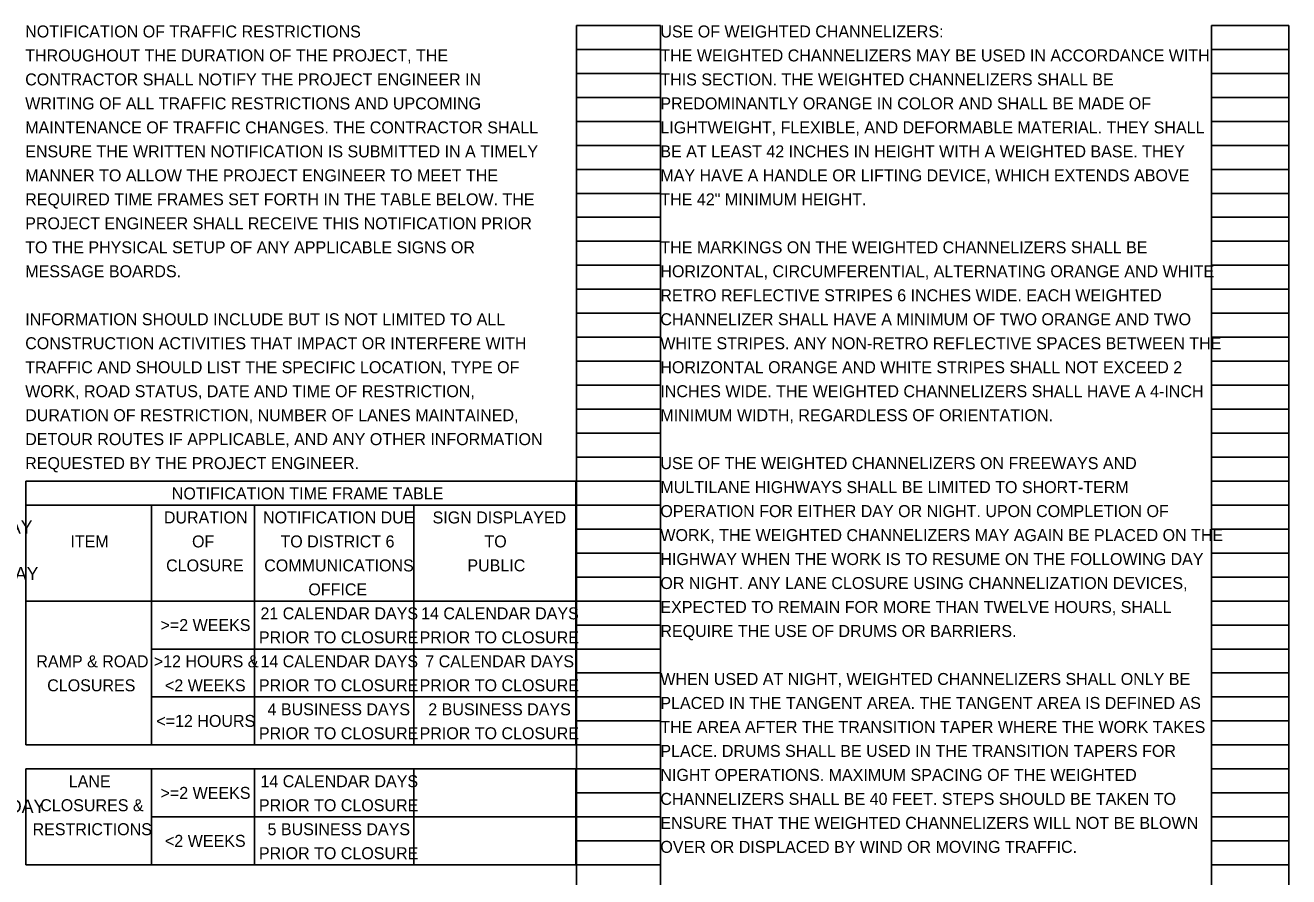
# Model space of a CAD drawing. Extents: x 51924.2 to 51956.2, y 31431.6 to 31530.7.
# Drawn here: x 51941.45 to 51956.21, y 31520.75 to 31530.69 of the extents above; entities that cross this region are included whole.
import ezdxf

# ---------------------------------------------------------------- set-up
doc = ezdxf.new("R2010")
doc.units = 0
doc.layers.add('SH_Data', color=7, linetype='Continuous')
doc.layers.add('SH_Text', color=7, linetype='Continuous')

msp = doc.modelspace()

# ---------------------------------------------------------------- linework, layer by layer
at = {"layer": 'SH_Data'}
for p, q in [((51947.888, 31510.524), (51947.888, 31530.684)), ((51947.888, 31530.684), (51948.868, 31530.684)), ((51948.868, 31510.524), (51948.868, 31530.684)), ((51955.308, 31510.524), (51955.308, 31530.684)), ((51955.308, 31530.684), (51956.208, 31530.684)), ((51956.208, 31510.524), (51956.208, 31530.684)), ((51947.888, 31530.404), (51948.868, 31530.404)), ((51955.308, 31530.404), (51956.208, 31530.404)), ((51947.888, 31530.124), (51948.868, 31530.124)), ((51955.308, 31530.124), (51956.208, 31530.124)), ((51947.888, 31529.844), (51948.868, 31529.844)), ((51955.308, 31529.844), (51956.208, 31529.844)), ((51947.888, 31529.564), (51948.868, 31529.564)), ((51955.308, 31529.564), (51956.208, 31529.564)), ((51947.888, 31529.284), (51948.868, 31529.284)), ((51955.308, 31529.284), (51956.208, 31529.284)), ((51947.888, 31529.004), (51948.868, 31529.004)), ((51955.308, 31529.004), (51956.208, 31529.004)), ((51947.888, 31528.724), (51948.868, 31528.724)), ((51955.308, 31528.724), (51956.208, 31528.724)), ((51947.888, 31528.444), (51948.868, 31528.444)), ((51955.308, 31528.444), (51956.208, 31528.444)), ((51947.888, 31528.164), (51948.868, 31528.164)), ((51955.308, 31528.164), (51956.208, 31528.164)), ((51947.888, 31527.884), (51948.868, 31527.884)), ((51955.308, 31527.884), (51956.208, 31527.884)), ((51947.888, 31527.604), (51948.868, 31527.604)), ((51955.308, 31527.604), (51956.208, 31527.604)), ((51947.888, 31527.324), (51948.868, 31527.324)), ((51955.308, 31527.324), (51956.208, 31527.324)), ((51947.888, 31527.044), (51948.868, 31527.044)), ((51955.308, 31527.044), (51956.208, 31527.044)), ((51947.888, 31526.764), (51948.868, 31526.764)), ((51955.308, 31526.764), (51956.208, 31526.764)), ((51947.888, 31526.484), (51948.868, 31526.484)), ((51955.308, 31526.484), (51956.208, 31526.484)), ((51947.888, 31526.204), (51948.868, 31526.204)), ((51955.308, 31526.204), (51956.208, 31526.204)), ((51947.888, 31525.924), (51948.868, 31525.924)), ((51955.308, 31525.924), (51956.208, 31525.924)), ((51947.888, 31525.644), (51948.868, 31525.644)), ((51955.308, 31525.644), (51956.208, 31525.644)), ((51941.457, 31525.364), (51947.88, 31525.364)), ((51941.457, 31525.364), (51941.457, 31522.284)), ((51947.88, 31525.364), (51947.88, 31522.284)), ((51947.888, 31525.364), (51948.868, 31525.364)), ((51955.308, 31525.364), (51956.208, 31525.364)), ((51941.457, 31525.084), (51947.88, 31525.084)), ((51942.923, 31525.084), (51942.923, 31522.284)), ((51944.125, 31525.084), (51944.125, 31522.284)), ((51945.986, 31525.084), (51945.986, 31522.284)), ((51947.888, 31525.084), (51948.868, 31525.084)), ((51955.308, 31525.084), (51956.208, 31525.084)), ((51947.888, 31524.804), (51948.868, 31524.804)), ((51955.308, 31524.804), (51956.208, 31524.804)), ((51947.888, 31524.524), (51948.868, 31524.524)), ((51955.308, 31524.524), (51956.208, 31524.524)), ((51947.888, 31524.244), (51948.868, 31524.244)), ((51955.308, 31524.244), (51956.208, 31524.244)), ((51941.457, 31523.964), (51947.88, 31523.964)), ((51947.888, 31523.964), (51948.868, 31523.964)), ((51955.308, 31523.964), (51956.208, 31523.964)), ((51947.888, 31523.684), (51948.868, 31523.684)), ((51955.308, 31523.684), (51956.208, 31523.684)), ((51942.923, 31523.404), (51947.88, 31523.404)), ((51947.888, 31523.404), (51948.868, 31523.404)), ((51955.308, 31523.404), (51956.208, 31523.404)), ((51947.888, 31523.124), (51948.868, 31523.124)), ((51955.308, 31523.124), (51956.208, 31523.124)), ((51942.923, 31522.844), (51947.88, 31522.844)), ((51947.888, 31522.844), (51948.868, 31522.844)), ((51955.308, 31522.844), (51956.208, 31522.844)), ((51947.888, 31522.564), (51948.868, 31522.564)), ((51955.308, 31522.564), (51956.208, 31522.564)), ((51941.457, 31522.284), (51947.88, 31522.284)), ((51947.888, 31522.284), (51948.868, 31522.284)), ((51955.308, 31522.284), (51956.208, 31522.284)), ((51941.457, 31522.004), (51947.88, 31522.004)), ((51941.457, 31522.004), (51941.457, 31520.884)), ((51942.923, 31522.004), (51942.923, 31520.884)), ((51944.125, 31522.004), (51944.125, 31520.884)), ((51945.986, 31522.004), (51945.986, 31520.884)), ((51947.88, 31522.004), (51947.88, 31520.884)), ((51947.888, 31522.004), (51948.868, 31522.004)), ((51955.308, 31522.004), (51956.208, 31522.004)), ((51947.888, 31521.724), (51948.868, 31521.724)), ((51955.308, 31521.724), (51956.208, 31521.724)), ((51942.923, 31521.444), (51947.88, 31521.444)), ((51947.888, 31521.444), (51948.868, 31521.444)), ((51955.308, 31521.444), (51956.208, 31521.444)), ((51947.888, 31521.164), (51948.868, 31521.164)), ((51955.308, 31521.164), (51956.208, 31521.164)), ((51941.457, 31520.884), (51947.88, 31520.884)), ((51947.888, 31520.884), (51948.868, 31520.884)), ((51955.308, 31520.884), (51956.208, 31520.884))]:
    msp.add_line(p, q, dxfattribs=at)

# ---------------------------------------------------------------- texts
for s, height, p in [('NOTIFICATION TIME FRAME TABLE', 0.14, (51943.161, 31525.15)), ('12:00 NOON FRIDAY THROUGH 6:00 AM MONDAY', 0.154, (51936.647, 31524.752)), ('DURATION', 0.14, (51943.068, 31524.87)), ('NOTIFICATION DUE', 0.14, (51944.227, 31524.87)), ('SIGN DISPLAYED', 0.14, (51946.207, 31524.87)), ('ITEM', 0.14, (51941.976, 31524.59)), ('OF', 0.14, (51943.397, 31524.59)), ('TO DISTRICT 6', 0.14, (51944.43, 31524.59)), ('TO', 0.14, (51946.813, 31524.59)), ('12:00 NOON FRIDAY THROUGH 6:00 AM TUESDAY', 0.154, (51936.647, 31524.208)), ('CLOSURE', 0.14, (51943.094, 31524.31)), ('COMMUNICATIONS', 0.14, (51944.24, 31524.31)), ('PUBLIC', 0.14, (51946.614, 31524.31)), (' OFFICE', 0.14, (51944.704, 31524.03)), ('21 CALENDAR DAYS', 0.14, (51944.196, 31523.75)), ('14 CALENDAR DAYS', 0.14, (51946.073, 31523.75)), ('>=2 WEEKS', 0.14, (51943.029, 31523.614)), ('PRIOR TO CLOSURE', 0.14, (51944.178, 31523.47)), ('PRIOR TO CLOSURE', 0.14, (51946.055, 31523.47)), ('RAMP & ROAD', 0.14, (51941.578, 31523.19)), ('>12 HOURS &', 0.14, (51942.95, 31523.19)), ('14 CALENDAR DAYS', 0.14, (51944.196, 31523.19)), ('7 CALENDAR DAYS', 0.14, (51946.122, 31523.19)), ('CLOSURES', 0.14, (51941.705, 31522.91)), ('<2 WEEKS', 0.14, (51943.081, 31522.91)), ('PRIOR TO CLOSURE', 0.14, (51944.178, 31522.91)), ('PRIOR TO CLOSURE', 0.14, (51946.055, 31522.91)), ('4 BUSINESS DAYS', 0.14, (51944.279, 31522.63)), ('2 BUSINESS DAYS', 0.14, (51946.157, 31522.63)), ('<=12 HOURS', 0.14, (51942.98, 31522.494)), ('PRIOR TO CLOSURE', 0.14, (51944.178, 31522.35)), ('PRIOR TO CLOSURE', 0.14, (51946.055, 31522.35)), ('LANE', 0.14, (51941.956, 31521.79)), ('14 CALENDAR DAYS', 0.14, (51944.196, 31521.79)), ('>=2 WEEKS', 0.14, (51943.029, 31521.654)), ('6:00 AM WEDNESDAY THROUGH 6:00 AM MONDAY', 0.154, (51936.647, 31521.491)), ('CLOSURES &', 0.14, (51941.624, 31521.51)), ('PRIOR TO CLOSURE', 0.14, (51944.178, 31521.51)), ('RESTRICTIONS', 0.14, (51941.534, 31521.23)), ('5 BUSINESS DAYS', 0.14, (51944.279, 31521.23)), ('<2 WEEKS', 0.14, (51943.081, 31521.094)), ('PRIOR TO CLOSURE', 0.14, (51944.178, 31520.95))]:
    msp.add_text(s, height=height, dxfattribs=at).set_placement(p)
at = {"layer": 'SH_Text'}
for s, p in [('NOTIFICATION OF TRAFFIC RESTRICTIONS', (51941.448, 31530.544)), ('USE OF WEIGHTED CHANNELIZERS:', (51948.868, 31530.544)), ('THROUGHOUT THE DURATION OF THE PROJECT, THE ', (51941.448, 31530.264)), ('THE WEIGHTED CHANNELIZERS MAY BE USED IN ACCORDANCE WITH ', (51948.868, 31530.264)), ('CONTRACTOR SHALL NOTIFY THE PROJECT ENGINEER IN ', (51941.448, 31529.984)), ('THIS SECTION. THE WEIGHTED CHANNELIZERS SHALL BE ', (51948.868, 31529.984)), ('WRITING OF ALL TRAFFIC RESTRICTIONS AND UPCOMING ', (51941.448, 31529.704)), ('PREDOMINANTLY ORANGE IN COLOR AND SHALL BE MADE OF ', (51948.868, 31529.704)), ('MAINTENANCE OF TRAFFIC CHANGES. THE CONTRACTOR SHALL ', (51941.448, 31529.424)), ('LIGHTWEIGHT, FLEXIBLE, AND DEFORMABLE MATERIAL. THEY SHALL ', (51948.868, 31529.424)), ('ENSURE THE WRITTEN NOTIFICATION IS SUBMITTED IN A TIMELY ', (51941.448, 31529.144)), ('BE AT LEAST 42 INCHES IN HEIGHT WITH A WEIGHTED BASE. THEY ', (51948.868, 31529.144)), ('MANNER TO ALLOW THE PROJECT ENGINEER TO MEET THE ', (51941.448, 31528.864)), ('MAY HAVE A HANDLE OR LIFTING DEVICE, WHICH EXTENDS ABOVE ', (51948.868, 31528.864)), ('REQUIRED TIME FRAMES SET FORTH IN THE TABLE BELOW. THE ', (51941.448, 31528.584)), ('THE 42" MINIMUM HEIGHT.', (51948.868, 31528.584)), ('PROJECT ENGINEER SHALL RECEIVE THIS NOTIFICATION PRIOR ', (51941.448, 31528.304)), ('TO THE PHYSICAL SETUP OF ANY APPLICABLE SIGNS OR ', (51941.448, 31528.024)), ('THE MARKINGS ON THE WEIGHTED CHANNELIZERS SHALL BE ', (51948.868, 31528.024)), ('MESSAGE BOARDS. ', (51941.448, 31527.744)), ('HORIZONTAL, CIRCUMFERENTIAL, ALTERNATING ORANGE AND WHITE ', (51948.868, 31527.744)), ('RETRO REFLECTIVE STRIPES 6 INCHES WIDE. EACH WEIGHTED ', (51948.868, 31527.464)), ('INFORMATION SHOULD INCLUDE BUT IS NOT LIMITED TO ALL ', (51941.448, 31527.184)), ('CHANNELIZER SHALL HAVE A MINIMUM OF TWO ORANGE AND TWO ', (51948.868, 31527.184)), ('CONSTRUCTION ACTIVITIES THAT IMPACT OR INTERFERE WITH ', (51941.448, 31526.904)), ('WHITE STRIPES. ANY NON-RETRO REFLECTIVE SPACES BETWEEN THE ', (51948.868, 31526.904)), ('TRAFFIC AND SHOULD LIST THE SPECIFIC LOCATION, TYPE OF ', (51941.448, 31526.624)), ('HORIZONTAL ORANGE AND WHITE STRIPES SHALL NOT EXCEED 2 ', (51948.868, 31526.624)), ('WORK, ROAD STATUS, DATE AND TIME OF RESTRICTION, ', (51941.448, 31526.344)), ('INCHES WIDE. THE WEIGHTED CHANNELIZERS SHALL HAVE A 4-INCH ', (51948.868, 31526.344)), ('DURATION OF RESTRICTION, NUMBER OF LANES MAINTAINED, ', (51941.448, 31526.064)), ('MINIMUM WIDTH, REGARDLESS OF ORIENTATION.', (51948.868, 31526.064)), ('DETOUR ROUTES IF APPLICABLE, AND ANY OTHER INFORMATION ', (51941.448, 31525.784)), ('REQUESTED BY THE PROJECT ENGINEER.', (51941.448, 31525.504)), ('USE OF THE WEIGHTED CHANNELIZERS ON FREEWAYS AND ', (51948.868, 31525.504)), ('MULTILANE HIGHWAYS SHALL BE LIMITED TO SHORT-TERM ', (51948.868, 31525.224)), ('OPERATION FOR EITHER DAY OR NIGHT. UPON COMPLETION OF ', (51948.868, 31524.944)), ('WORK, THE WEIGHTED CHANNELIZERS MAY AGAIN BE PLACED ON THE ', (51948.868, 31524.664)), ('HIGHWAY WHEN THE WORK IS TO RESUME ON THE FOLLOWING DAY ', (51948.868, 31524.384)), ('OR NIGHT. ANY LANE CLOSURE USING CHANNELIZATION DEVICES, ', (51948.868, 31524.104)), ('EXPECTED TO REMAIN FOR MORE THAN TWELVE HOURS, SHALL ', (51948.868, 31523.824)), ('REQUIRE THE USE OF DRUMS OR BARRIERS.', (51948.868, 31523.544)), ('WHEN USED AT NIGHT, WEIGHTED CHANNELIZERS SHALL ONLY BE ', (51948.868, 31522.984)), ('PLACED IN THE TANGENT AREA. THE TANGENT AREA IS DEFINED AS ', (51948.868, 31522.704)), ('THE AREA AFTER THE TRANSITION TAPER WHERE THE WORK TAKES ', (51948.868, 31522.424)), ('PLACE. DRUMS SHALL BE USED IN THE TRANSITION TAPERS FOR ', (51948.868, 31522.144)), ('NIGHT OPERATIONS. MAXIMUM SPACING OF THE WEIGHTED ', (51948.868, 31521.864)), ('CHANNELIZERS SHALL BE 40 FEET. STEPS SHOULD BE TAKEN TO ', (51948.868, 31521.584)), ('ENSURE THAT THE WEIGHTED CHANNELIZERS WILL NOT BE BLOWN ', (51948.868, 31521.304)), ('OVER OR DISPLACED BY WIND OR MOVING TRAFFIC.', (51948.868, 31521.024))]:
    msp.add_text(s, height=0.14, dxfattribs=at).set_placement(p)

doc.saveas('drawing.dxf')
